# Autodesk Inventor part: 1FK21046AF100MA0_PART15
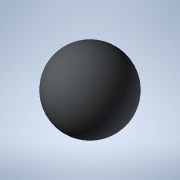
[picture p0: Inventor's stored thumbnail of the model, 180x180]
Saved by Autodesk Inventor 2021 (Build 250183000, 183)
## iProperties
Created: 2025-04
Part Number: 1FK21046AF100MA0_PART15
Material: Generic
Catalog Web Link: www.3dfindit.com
Description: -Servo synchronous motor
Document SubType Name: Modeling
Designer: psAdmin
Mass: 0.137258 g
Surface Area: 1.2868 cm^2
Volume: 0.137258 cm^3
Density: 1 g/cm^3
Appearance: PSOLRGB-212-217-219
Category: PARTsolutions
Title: 1FK21046AF100MA0_PART15
Author: Cadenas PARTsolutions
Comments: Servo synchronous motor
Sending System: PARTsolutions
Preprocessor: ST-DEVELOPER v19.3
PSOL_IDENT_0: {$CADENAS_DATA/23d-libs/siemens_ag/_cat_/4f/2b/1fk21046af100ma0.prj},216 {VTYP=3D},{NB=1FK21046AF100
PSOL_IDENT_1: MA0_PART15},{LINA=1FK21046AF100MA0_PART15},{NN=1FK21046AF100MA0_PART15},{NOPRJ=TRUE},{DATE=19.08.202
PSOL_IDENT_2: 5 14:00:37},{GEOMDATE=30.07.2025 02:01:06},{VERSION=},{LINEID=10},{WBVAR=},{WBNUMERIC=}  {NB=1FK2104
PSOL_IDENT_3: 6AF100MA0_PART15},{LINA=1FK21046AF100MA0_PART15},{KT=DUMMY},{PREVIEW=../../../_pool_/cb/72/p_d211_xx
PSOL_IDENT_4: _00434j.png},{DESCSHORT=SIMOTICS S-1FK2 HD, SINAMICS S210 3AC 400V-480V, 3.2 Nm, 3000 rpm},{DESCLONG=
PSOL_IDENT_5: SIMOTICS S-1FK2 HD servo motor M0=3.2 Nm; PN = 1 kW at nN=3000 rpm (380-480 V); PN = 0.5 kW at nN=15
PSOL_IDENT_6: 00 rpm (200-240 V); with holding brake; degree of protection IP64; cylindrical shaft D19x40mm; absol
PSOL_IDENT_7: ute encoder 22-bit + 12-bit multiturn (encoder AM22DQC); with OCC interface; plug size M17, rotatabl
PSOL_IDENT_8: e; SIMOTICS S-1FK2 servomotorfor a wide range of uses in industrial environments. SIMOTICS S‑1FK2 se
PSOL_IDENT_9: rvomotors are compact synchronous motors with a high dynamic performance that set themselves apart a
PSOL_IDENT_10: s a result of their high power density, degree of protection and overload capability. The motors are
PSOL_IDENT_11: available in two variants: as High Dynamic variant (highest dynamic performance as a result of the
PSOL_IDENT_12: low intrinsic moment of inertia for applications demanding a high dynamic performance with low moved
PSOL_IDENT_13: masses) - and as Compact variant (precise and stable closed-loop control for medium up to large mov
PSOL_IDENT_14: ed masses as a result of a medium intrinsic moment of inertia). SIMOTICSS‑1FK2 servomotors fully exp
PSOL_IDENT_15: loit their strengths in a system with the SINAMICSS210 frequency converter and simple connection usi
PSOL_IDENT_16: ng the one cable connection (OCC). Advantages include the short control and positioning times, fast
PSOL_IDENT_17: and precise correction of disturbing quantities as well as stable control with a high dynamic perfor
PSOL_IDENT_18: mance. The servo motors can be configured to address a wide range of requirements. For example with
PSOL_IDENT_19: and without holding brake, IP64 or IP65 degree of protection, singleturn or multiturn absolute encod
PSOL_IDENT_20: ers - to name just a few. Further, the servomotors are available in different shaft heights extendin
PSOL_IDENT_21: g from 20 to 100. A shaft sealing ring is available to achieve an IP65 degree of protection and for
PSOL_IDENT_22: subsequent mounting at the motor or as spare part. SIMOTICS - the optimum motor for each and every m
PSOL_IDENT_23: otion control application.},{INTNO=195125049673},{SUPPLIERALTNO=1FK2104-6AF10-0MA0},{MANUID=1FK21046
PSOL_IDENT_24: AF100MA0},{MANUNAME=Siemens},{MANUTYPEDESC=Synchronous motor 1FK2-HD 3.2 NM},{AAU732=SIMOTICS},{AAO0
PSOL_IDENT_25: 57=S-1FK2},{AAU734=SIMOTICS S-1FK2 HD servo motor M0=3.2 Nm; PN = 1 kW at nN=3000 rpm (380-480 V); P
PSOL_IDENT_26: N = 0.5 kW at nN=1500 rpm (200-240 V); with holding brake; degree of protection IP64; cylindrical sh
PSOL_IDENT_27: aft D19x40mm; absolute encoder 22-bit + 12-bit multiturn (encoder AM22DQC); with OCC interface; plug
PSOL_IDENT_28: size M17, rotatable;},{AAW338=Synchronous motor 1FK2-HD 3.2 NM},{AAO742=SIMOTICS},{AAO663=404294869
PSOL_IDENT_29: 4534},{NOCUPEROU=1},{PRICEQUANTITY=1},{QUANTITYMIN=1},{QUANTITYINT=1},{CTN=85015220},{COO=DE},{AAO67
PSOL_IDENT_30: 6=1FK2104-6AF10-0MA0},{AAO677=Siemens AG},{ORDERUNIT=C62},{CONTENTUNIT=C62}
NB: 1FK21046AF100MA0_PART15
NT: Servo synchronous motor
NBSYN: $MANUID._PART15
LINA: 1FK21046AF100MA0_PART15
CATALOG: SIEMENS
PREVIEW: ../../../_pool_/cb/72/p_d211_xx_00434j.png
DESCSHORT: SIMOTICS S-1FK2 HD, SINAMICS S210 3AC 400V-480V, 3.2 Nm, 3000 rpm
DESCLONG: SIMOTICS S-1FK2 HD servo motor M0=3.2 Nm; PN = 1 kW at nN=3000 rpm (380-480 V); PN = 0.5 kW at nN=1500 rpm (200-240 V); with holding brake; degree of protection
INTNO: 195125049673
SUPPLIERALTNO: 1FK2104-6AF10-0MA0
MANUID: 1FK21046AF100MA0
MANUNAME: Siemens
MANUTYPEDESC: Synchronous motor 1FK2-HD 3.2 NM
AAU732: SIMOTICS
AAO057: S-1FK2
AAU734: SIMOTICS S-1FK2 HD servo motor M0=3.2 Nm; PN = 1 kW at nN=3000 rpm (380-480 V); PN = 0.5 kW at nN=1500 rpm (200-240 V); with holding brake; degree of protection
AAW338: Synchronous motor 1FK2-HD 3.2 NM
AAO742: SIMOTICS
AAO663: 4042948694534.0
NOCUPEROU: 1
PRICEQUANTITY: 1
QUANTITYMIN: 1
QUANTITYINT: 1
CTN: 85015220
COO: DE
ARTICLENO: 1FK21046AF100MA0_PART15
BOMINFO: 1FK21046AF100MA0_PART15
CREATOR: CADENAS GmbH
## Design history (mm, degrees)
feature "2025_04_17_14_59_39_0177"
body "Solid1"
